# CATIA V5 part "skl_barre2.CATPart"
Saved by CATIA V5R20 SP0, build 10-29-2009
Part number: skl_barre2
Publications: "Barre_2", "Axe_Pivot_b2b4", "Axe_Pivot_b2b6"
Bounding box of the stored display mesh (mm): x -159.748 to 0, y -440 to 58.143, z 0 to 20
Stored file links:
  C:\Users\Matthieu\Desktop\IFMA\Cours 2A\Thinkmotion\skl_barre2.CATPart
  C:\Users\Matthieu\Desktop\IFMA\Cours 2A\Thinkmotion\skl_IAO_bis.CATProduct
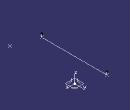
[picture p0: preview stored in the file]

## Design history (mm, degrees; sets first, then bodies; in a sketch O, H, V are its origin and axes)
AxisSystem1: origin (0, 0, 0), X (1, 0, 0), Y (0, 1, 0), Z (0, 0, 1)
Set1
  Point1 "Point.C": linked copy from another document
  Point2 "Point.D": linked copy from another document
  Plane1 "Plan_Ref": linked copy from another document
  Point3 "Point.B": linked copy from another document
Body1 (main body)
  Line1 "Barre_2": type PtPt, FirstPoint Point1, SecondPoint Point2
  Line2 "Axe_Pivot_b2b4": type Normal, RefPoint Point1, RefSkin Plane1, Start 0, End 20
  Line3 "Axe_Pivot_b2b6": type Normal, RefPoint Point2, RefSkin Plane1, Start 0, End 20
